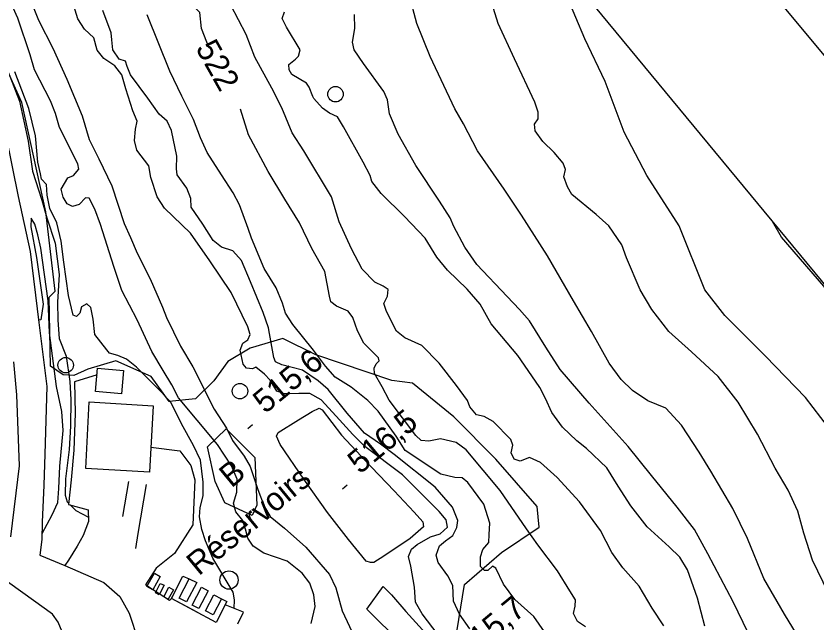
# Model space of a CAD drawing. Extents: x 347059 to 352153, y 6073752 to 6078601.
# Drawn here: x 349755.8 to 349911.2, y 6077759.6 to 6077877.3 of the extents above; entities that cross this region are included whole.
import ezdxf

# ---------------------------------------------------------------- set-up
doc = ezdxf.new("R2010")
doc.units = 0
for name, color, linetype in [('Level 1', 7, 'Continuous'), ('Level 19', 7, 'Continuous'), ('Level 2', 7, 'Continuous'), ('Level 21', 7, 'Continuous'), ('Level 3', 7, 'Continuous'), ('Level 31', 7, 'Continuous'), ('Level 33', 7, 'Continuous'), ('Level 36', 7, 'Continuous'), ('Level 37', 7, 'Continuous'), ('Level 44', 7, 'Continuous'), ('Level 60', 7, 'Continuous')]:
    doc.layers.add(name, color=color, linetype=linetype)

msp = doc.modelspace()

# ---------------------------------------------------------------- linework, layer by layer
at = {"layer": 'Level 1'}
for points in [[(349908.65, 6077755.14), (349904.89, 6077761.25), (349900.85, 6077768.19), (349897.7, 6077775.98), (349894.86, 6077781.79), (349890.56, 6077789.03), (349888.3, 6077792.7), (349884.9, 6077797.91), (349881.88, 6077801.21), (349878.39, 6077802.67), (349875.39, 6077804.67), (349873.2, 6077806.81), (349870.83, 6077809.98), (349867.44, 6077816.13), (349863.96, 6077822.07), (349858.87, 6077830.74), (349853.84, 6077838.69), (349850.49, 6077843.68), (349845.34, 6077851.13), (349842.59, 6077856.35), (349840.93, 6077859.31), (349836.12, 6077869.41), (349833.56, 6077875.84), (349831.65, 6077882.93)], [(349858.31, 6077757.85), (349856.26, 6077760.8), (349852.56, 6077764.11), (349850.36, 6077767.07), (349848.84, 6077770.19), (349848.23, 6077770.6), (349847.33, 6077769.74), (349846.67, 6077769.72), (349845.88, 6077770.52), (349845.92, 6077772.41), (349846.35, 6077773.83), (349847.51, 6077775.18), (349847.59, 6077776.7), (349847.73, 6077778.94), (349846.56, 6077782.61), (349843.46, 6077786.81), (349842.31, 6077787.72), (349840.92, 6077787.77), (349838.21, 6077788.44), (349831.28, 6077793.05), (349829.51, 6077795.83), (349826.03, 6077800.64), (349824.04, 6077802.71), (349820.79, 6077805.32), (349817.69, 6077807.27), (349815.79, 6077809.4), (349813.46, 6077812.51), (349809.49, 6077817.45), (349808.03, 6077819.68), (349807.49, 6077821.62), (349806.25, 6077824.57), (349803.92, 6077828.33), (349801.43, 6077834.22), (349800.81, 6077836.1), (349799.15, 6077840.68), (349797.91, 6077842.97), (349795.63, 6077846.51), (349792.84, 6077850.83), (349791.59, 6077853.63), (349790.19, 6077857.24), (349787.93, 6077861.72), (349785.64, 6077866.58), (349781.24, 6077877.5)], [(349798.1, 6077762.36), (349798.18, 6077764.03), (349797.89, 6077765.52), (349793.98, 6077772.17), (349792.55, 6077775.52), (349791.81, 6077777.71), (349791.39, 6077780.17), (349791.49, 6077781.99), (349792.08, 6077784.21), (349792.05, 6077786.85), (349791.59, 6077791.14), (349790.18, 6077793.98), (349787.87, 6077798.21), (349785.84, 6077802.27), (349783.99, 6077804.34), (349779.16, 6077809.16), (349777.18, 6077810.72), (349775.49, 6077811.46), (349773.91, 6077811.89), (349773.39, 6077812.52), (349771.03, 6077815.51), (349770.74, 6077818.47), (349770.3, 6077820.78), (349769.49, 6077821.44), (349768.47, 6077820.87), (349768.13, 6077819.65), (349767.48, 6077818.98), (349766.84, 6077819.25), (349765.97, 6077823.06), (349765.06, 6077829.52), (349764.51, 6077833.59), (349763.69, 6077837.18), (349762.34, 6077839.94), (349761.79, 6077842.55), (349761.7, 6077844.61), (349760.7, 6077845.65), (349760.51, 6077846.69), (349759.99, 6077848.93), (349759.54, 6077854.02), (349758.23, 6077859.34), (349755.55, 6077866.46)]]:
    msp.add_lwpolyline(points, dxfattribs=at)
at = {"layer": 'Level 19'}
for points in [[(349771.49, 6077807.7), (349767.11, 6077806.35), (349767.26, 6077800.2), (349767, 6077793.1), (349766.48, 6077787.3), (349765.98, 6077782.56), (349769.79, 6077781.53), (349769.83, 6077779.22), (349768.81, 6077776.55), (349767.6, 6077774.47), (349765.96, 6077771.73), (349765.22, 6077770.75)], [(349781.94, 6077793.68), (349787.58, 6077792.98), (349789.66, 6077790.13), (349790.44, 6077787.3), (349790.08, 6077778.61), (349786.51, 6077773.04), (349782.98, 6077770.22), (349780.89, 6077766.97)], [(349785.96, 6077764.32), (349785.56, 6077763.9), (349782.22, 6077766.08), (349780.89, 6077766.97)], [(349839.8, 6077720.48), (349843.02, 6077722.81), (349844.25, 6077724.74), (349845.07, 6077727.52), (349844.33, 6077733.95), (349842.65, 6077740.78), (349839.99, 6077746.27), (349834.89, 6077751.73), (349827.89, 6077758.22), (349826.5, 6077759.6), (349823.84, 6077762.24), (349826.99, 6077766.62), (349828.64, 6077765), (349831.38, 6077761.83), (349837.88, 6077754.69), (349841.92, 6077749.61), (349845.38, 6077744.5), (349847.54, 6077739.87), (349849.18, 6077733.08), (349850.79, 6077727.76), (349853.29, 6077724.24), (349853.4, 6077722.83), (349851.52, 6077718.63), (349848.41, 6077714.48)], [(349798.79, 6077759.43), (349799.89, 6077761.64), (349796.32, 6077763.08)]]:
    msp.add_lwpolyline(points, dxfattribs=at)
at = {"layer": 'Level 2'}
for points in [[(349793.23, 6077871.05), (349791.73, 6077874.87), (349791.45, 6077877.94), (349789.07, 6077880.47), (349786.76, 6077882.12), (349786.1, 6077883.56), (349785.54, 6077886.8), (349784.04, 6077892.3), (349783.35, 6077895.56), (349782.73, 6077899.68), (349782.18, 6077903.72), (349780.37, 6077908.95), (349779.46, 6077914.55), (349778.96, 6077922.72), (349778.76, 6077928.76), (349777.82, 6077935.52), (349777.06, 6077940.3), (349777.08, 6077950.9), (349776.37, 6077961.41), (349776.28, 6077965.09)], [(349756.14, 6077876.85), (349753.13, 6077883.55), (349748.75, 6077893.51), (349744.12, 6077902.32), (349742.88, 6077906.88), (349742.88, 6077911.27), (349743, 6077920.69), (349743.07, 6077924.34), (349743.22, 6077931.78), (349743.83, 6077937.21), (349743.8, 6077938.24)], [(349952.21, 6077714.01), (349940.56, 6077731.19), (349933.43, 6077744.22), (349930.23, 6077752.86), (349926.1, 6077763.89), (349922.2, 6077771.44), (349920.24, 6077777.95), (349920.11, 6077782.58), (349917.9, 6077790.98), (349914.87, 6077795.57), (349908.97, 6077803.29), (349901.21, 6077811.32), (349893.29, 6077819.22), (349889.43, 6077824.16), (349884.43, 6077836.56), (349878.15, 6077846.32), (349873.77, 6077854.77), (349870.11, 6077864.59), (349866.15, 6077872.85), (349862.63, 6077881.22), (349860, 6077888.93)], [(349913.39, 6077765.36), (349910.32, 6077771.76), (349908.66, 6077776.96), (349907.48, 6077781.25), (349905.56, 6077785.31), (349903.08, 6077789.57), (349899.67, 6077796.22), (349895.86, 6077802.4), (349891.99, 6077807.36), (349886.81, 6077812.14), (349882.41, 6077816.13), (349879.13, 6077820.38), (349876.9, 6077824.18), (349874.25, 6077830.4), (349873.34, 6077832.93), (349870.8, 6077836.62), (349868.33, 6077838.78), (349863.64, 6077842.65), (349862.77, 6077844.17), (349862.09, 6077846.1), (349862.38, 6077847.52), (349861.92, 6077848.71), (349860.17, 6077850.81), (349857.98, 6077852.95), (349856.52, 6077855.02), (349856.36, 6077856.33), (349857.11, 6077857.35), (349857.1, 6077858.65), (349856.42, 6077860.58), (349852.47, 6077869), (349849.3, 6077875.84), (349847.44, 6077881.91)], [(349747.91, 6077880.11), (349751.44, 6077872.61), (349754.58, 6077865.59), (349756.45, 6077860.74), (349758.12, 6077853.03), (349758.94, 6077847.17), (349760.75, 6077841.58), (349761.73, 6077838.12), (349763.38, 6077833.21), (349764.11, 6077827.13), (349763.8, 6077821.8), (349763.89, 6077818.27), (349764.13, 6077814.73), (349765.49, 6077811.31), (349766.18, 6077806.41), (349766.42, 6077802.87), (349766.36, 6077797.74), (349766.06, 6077793.21), (349765.35, 6077787.55), (349765.32, 6077784.33), (349765.71, 6077783.05), (349766, 6077782.76)], [(349758.95, 6077879.35), (349760.13, 6077876.47), (349762.9, 6077871.05), (349765.6, 6077865.04), (349768.57, 6077857.92), (349769.95, 6077853.35), (349771.85, 6077849.6), (349774.34, 6077844.34), (349776.77, 6077837.05), (349777.97, 6077834.31), (349779.28, 6077831.28), (349781.8, 6077826.31), (349784.19, 6077820.84), (349784.95, 6077818.8), (349787.7, 6077813.23), (349790.09, 6077809.22), (349794.2, 6077801.04), (349796.62, 6077797.32), (349797.78, 6077794.96), (349800.05, 6077791.91), (349801.17, 6077789.91), (349802.71, 6077785.46), (349803.93, 6077782.21), (349805.06, 6077780.21), (349807.85, 6077777.99), (349812.03, 6077774.26), (349816.58, 6077768.97), (349817.79, 6077766.37), (349819.04, 6077761.95), (349822.38, 6077754.86)], [(349812.76, 6077804.08), (349810.63, 6077804.05), (349807.84, 6077804), (349806.35, 6077804.5), (349805.09, 6077806.65), (349803.96, 6077807.85), (349802.33, 6077809.16), (349801.64, 6077808.85), (349800.48, 6077808.96), (349799.83, 6077809.74), (349799.29, 6077812.49), (349799.79, 6077813.83), (349800.73, 6077814.48), (349801.21, 6077815.53), (349800.77, 6077817.03), (349797.54, 6077823.66), (349793.38, 6077829.78), (349789.59, 6077835.15), (349784.58, 6077840.04), (349783.18, 6077842.2), (349781.94, 6077845.95), (349781.51, 6077848.25), (349779.24, 6077851.29), (349778.77, 6077853.16), (349778.98, 6077855.33), (349779.28, 6077856.91), (349778.45, 6077858.87), (349777.05, 6077863.15), (349776.29, 6077865.84), (349774.93, 6077867.64), (349772.8, 6077869.07), (349771.49, 6077870.64), (349770.84, 6077873.03), (349769.03, 6077874.72), (349767.77, 6077876.72), (349766.99, 6077879.27)], [(349831.2, 6077814.89), (349829.58, 6077816.19), (349827.62, 6077819.99), (349827.12, 6077821.56), (349827.84, 6077822.94), (349827.97, 6077824.24), (349827.02, 6077824.9), (349825.42, 6077825.69), (349822.96, 6077828.16), (349820.88, 6077832.11), (349818.48, 6077837.39), (349817, 6077842.24), (349811.61, 6077851.12), (349809.33, 6077854.65), (349807.33, 6077859.47), (349805.38, 6077863.26), (349802.11, 6077869.27), (349800.44, 6077873.7), (349797.43, 6077879.39)], [(349829.13, 6077792.22), (349826.48, 6077794.27), (349823.39, 6077796.37), (349820.04, 6077800.23), (349816.32, 6077804.86), (349814.37, 6077806.56), (349811.34, 6077808.57), (349807.35, 6077809.65), (349806.09, 6077810.2), (349805.8, 6077811.03), (349805.28, 6077813.91), (349804.76, 6077816.8), (349803.74, 6077819.8), (349801.25, 6077825.7), (349799.54, 6077829.86), (349797.83, 6077831.75), (349795.63, 6077832.46), (349794, 6077833.76), (349792.04, 6077836.92), (349789.73, 6077840.18), (349789.68, 6077841.86), (349788.93, 6077843.89), (349787.06, 6077846.46), (349786.89, 6077847.64), (349786.98, 6077850.11), (349785.94, 6077855.08), (349785.09, 6077856.9), (349783.55, 6077858.27), (349781.37, 6077861.37), (349778.01, 6077865.89), (349777.36, 6077867.47), (349777.03, 6077868.52), (349775.75, 6077868.92), (349774.54, 6077870.71), (349774.37, 6077872.69), (349774.21, 6077874.01), (349772.59, 6077878.37)], [(349819.32, 6077855.78), (349818.13, 6077857.7), (349816.6, 6077858.41), (349815.24, 6077859.4), (349813.53, 6077861.28), (349813.35, 6077861.66), (349812.66, 6077863.46), (349812.15, 6077864.23), (349809.26, 6077865.92), (349808.77, 6077866.84), (349808.73, 6077867.85), (349810, 6077868.9), (349810.56, 6077869.5), (349810.9, 6077870.7), (349808.28, 6077875.13), (349807.43, 6077876.8), (349807.85, 6077878.06)], [(349897.81, 6077757.66), (349894.91, 6077763.7), (349890, 6077772.96), (349887.41, 6077777.68), (349884.06, 6077782.02), (349879.06, 6077788.18), (349874.52, 6077793.79), (349866.98, 6077802.19), (349861.38, 6077808.76), (349858.6, 6077813.05), (349855.4, 6077818.18), (349853.43, 6077820.38), (349851.07, 6077822.9), (349845.21, 6077829.12), (349842.85, 6077832.44), (349840.7, 6077836.46), (349839.99, 6077838.11), (349837.92, 6077841.4), (349833.37, 6077848.31), (349829.9, 6077854.39), (349828.25, 6077858.29), (349827.87, 6077861), (349827.16, 6077862.66), (349823.19, 6077868.06), (349821.35, 6077870.75), (349821.05, 6077872.22), (349821.53, 6077874.86), (349821.44, 6077877.54)], [(349813.03, 6077759.49), (349813.79, 6077762.79), (349813.57, 6077765.01), (349812.77, 6077767.27), (349811.27, 6077769.23), (349808.41, 6077771.54), (349803.86, 6077773.11), (349801.78, 6077774.46), (349800.76, 6077776.02), (349800.27, 6077777.74), (349799.78, 6077779.47), (349798.4, 6077781.13), (349797.97, 6077782.78), (349798.63, 6077784.91), (349798.66, 6077787.47), (349797.59, 6077790.05), (349794.84, 6077794.17), (349790.9, 6077798.91), (349787.28, 6077803.25), (349785.99, 6077805.78), (349784.35, 6077808.56), (349782.14, 6077812.19), (349779.3, 6077818.37), (349776.33, 6077824.04), (349774.74, 6077828.71), (349772.16, 6077836.84), (349771.06, 6077839.79), (349769.95, 6077841.93), (349769.22, 6077842), (349767.99, 6077840.71), (349766.7, 6077840.32), (349765.72, 6077840.84), (349764.9, 6077842.16), (349764.54, 6077843.72), (349765.85, 6077845.87), (349766.93, 6077846.37), (349767.93, 6077847.59), (349767.74, 6077848.63), (349764.18, 6077855.67), (349763.42, 6077858.37), (349762.48, 6077860.8), (349759.33, 6077866.85), (349758.52, 6077869.77), (349756.14, 6077876.85)], [(349823.27, 6077813.81), (349822.05, 6077816.24), (349821.13, 6077818.79), (349820.23, 6077820.03), (349817.92, 6077821.03), (349816.84, 6077821.85), (349816.58, 6077822.96), (349815.67, 6077827.76), (349813.19, 6077832.19), (349810.76, 6077837.2), (349807.93, 6077841.73), (349804.67, 6077847.1), (349800.85, 6077854.25), (349799.33, 6077859.22)], [(349889.43, 6077758.94), (349888, 6077764.36), (349886.07, 6077769.89), (349884.56, 6077772.34), (349882.5, 6077774.34), (349878.21, 6077778.19), (349875.05, 6077782.31), (349872.58, 6077786.08), (349870.38, 6077789.68), (349866.46, 6077793.43), (349864.56, 6077794.9), (349861.83, 6077797.53), (349859.71, 6077800.39), (349858.52, 6077803.11), (349857.42, 6077805.23), (349855.82, 6077807.47), (349853.16, 6077811.47), (349847.94, 6077817.58), (349845.84, 6077821.39), (349843.29, 6077824.29), (349839.5, 6077828.02), (349837.42, 6077830.52), (349835.16, 6077834.2), (349831.14, 6077838.39), (349826.63, 6077842.84), (349824.82, 6077845.17), (349824.5, 6077846.35), (349823.15, 6077848.93), (349819.32, 6077855.78)], [(349760.82, 6077776.92), (349762.78, 6077780.57), (349763.88, 6077782.94), (349764.07, 6077785.64), (349764.28, 6077789.96), (349764.89, 6077796.88), (349764.67, 6077800.57), (349763.6, 6077805.44), (349762.27, 6077815.85), (349761.99, 6077822.04), (349760.57, 6077832.23), (349760.02, 6077834.85), (349759.41, 6077836.89), (349758.71, 6077838.05), (349758.62, 6077836.37), (349759.73, 6077830.47), (349761.04, 6077821.39), (349760.61, 6077818.35), (349760.15, 6077818.31)], [(349961.51, 6077714.06), (349959.39, 6077720.44), (349954.09, 6077728.4), (349948.46, 6077737.39), (349945.19, 6077743.87), (349941.09, 6077752.29), (349939.04, 6077760.82), (349936.09, 6077774.89), (349933.35, 6077782.33), (349928.41, 6077792.4), (349925.21, 6077801.03), (349918.12, 6077817.19), (349912.51, 6077824.87), (349904.32, 6077834.36), (349902.57, 6077837.42)], [(349881.49, 6077759.02), (349879.2, 6077762.42), (349876.7, 6077766.7), (349873.48, 6077770.25), (349871.37, 6077773.27), (349869.16, 6077777.53), (349865.11, 6077783.04), (349860.76, 6077787.77), (349857.54, 6077790.67), (349855.38, 6077791.66), (349853.56, 6077790.95), (349852.43, 6077791.34), (349851.82, 6077792.55), (349852.19, 6077794.04), (349851.79, 6077795.16), (349848.34, 6077798.66), (349846.61, 6077799.61), (349845.11, 6077799.96), (349843.81, 6077801.52), (349843.34, 6077802.73), (349841.22, 6077805.6), (349837.86, 6077809.95), (349834.48, 6077813.37), (349831.2, 6077814.89)], [(349866.26, 6077758.8), (349864.69, 6077759.88), (349863.96, 6077761.4), (349864.25, 6077762.83), (349864.3, 6077764.06), (349863.23, 6077765.83), (349860.83, 6077769.67), (349857.02, 6077774.73), (349854.84, 6077777.83), (349849.73, 6077785.25), (349843.14, 6077793.17), (349841.16, 6077794.58), (349838.16, 6077795.28), (349835.85, 6077794.83), (349834.4, 6077794.96), (349833.33, 6077795.93), (349828.16, 6077802.77), (349826.81, 6077805.36), (349825.32, 6077807.96), (349825.27, 6077808.98), (349825.65, 6077809.82), (349826.22, 6077810.42), (349826.13, 6077811.01), (349823.27, 6077813.81)], [(349837.69, 6077757.3), (349834.57, 6077761.37), (349833.25, 6077763.6), (349833.1, 6077766.53), (349832.4, 6077770.61), (349831.93, 6077772.48), (349832.51, 6077773.88), (349833.63, 6077774.81), (349836.19, 6077776.26), (349838.09, 6077776.89), (349839.46, 6077778.16), (349839.23, 6077779.57), (349837.86, 6077781.22), (349830.78, 6077788.27), (349823.47, 6077793.8), (349821.14, 6077796.12), (349817.9, 6077799.69), (349814.98, 6077802.87), (349812.76, 6077804.08)], [(349810.56, 6077798.95), (349813.22, 6077800.61), (349814.6, 6077801.22), (349815.15, 6077800.88), (349818.93, 6077796.02), (349821.77, 6077792.93), (349824.77, 6077789.82), (349829.15, 6077785.2), (349833, 6077781.07), (349834.72, 6077779.16), (349834.84, 6077778.2), (349832.27, 6077775.95), (349827.16, 6077772.53), (349825.21, 6077771.32), (349824.55, 6077771.3), (349823.69, 6077771.53), (349820.29, 6077775.77), (349816.19, 6077781.02), (349811.63, 6077787.48), (349807.01, 6077794.16), (349806.29, 6077795.82), (349806.66, 6077796.52), (349810.56, 6077798.95)], [(349843.81, 6077758.42), (349841.82, 6077761.29), (349840.68, 6077763.8), (349840.54, 6077766.87), (349839.55, 6077768.71), (349837.68, 6077771.28), (349837.31, 6077772.7), (349837.93, 6077774.54), (349839.13, 6077775.52), (349840.55, 6077776.56), (349841.29, 6077778.1), (349841.5, 6077779.47), (349840.43, 6077782.04), (349837.08, 6077785.91), (349829.13, 6077792.22)], [(349766.27, 6077782.48), (349767.39, 6077781.36), (349769.81, 6077780.08)]]:
    msp.add_lwpolyline(points, dxfattribs=at)
at = {"layer": 'Level 21'}
for points in [[(349753.81, 6077854.11), (349756.19, 6077842.27), (349758.54, 6077831.62), (349760.21, 6077817.83), (349761.76, 6077805.44), (349761.35, 6077792.33), (349761.19, 6077786.28), (349760.85, 6077779.11), (349760.8, 6077775.75), (349760.38, 6077772.74), (349765.22, 6077770.75), (349772.8, 6077767.45), (349775.93, 6077764.72), (349777.69, 6077761.45), (349779.48, 6077756.16)], [(349755.28, 6077810.24), (349755.83, 6077803.84), (349756.36, 6077790.06), (349754.7, 6077776.27)], [(349755.05, 6077661.53), (349755.8, 6077668.21), (349757.51, 6077679.77), (349759.69, 6077691.58), (349759.98, 6077693.54), (349761.34, 6077702.85), (349762.4, 6077714.09), (349762.74, 6077729.18), (349763.93, 6077738.11), (349765.13, 6077749.54), (349765.05, 6077757.1), (349763.93, 6077759.71), (349762.83, 6077761.28), (349759.17, 6077763.94), (349751.97, 6077769.01), (349744.46, 6077774.28), (349741.35, 6077775.37), (349730.35, 6077777.49), (349725.37, 6077777.26), (349724.23, 6077777.2), (349722.43, 6077775.55), (349721.54, 6077771.91)]]:
    msp.add_lwpolyline(points, dxfattribs=at)
at = {"layer": 'Level 3'}
for p, q in [((349800.75, 6077797.3), (349801.67, 6077798.07)), ((349819.11, 6077785.58), (349820.03, 6077786.35))]:
    msp.add_line(p, q, dxfattribs=at)
at = {"layer": 'Level 31'}
for points in [[(349771.6, 6077808.96), (349776.64, 6077808.52), (349776.24, 6077804), (349771.21, 6077804.45), (349771.6, 6077808.96)], [(349782.36, 6077801.67), (349781.69, 6077788.85), (349769.3, 6077789.5), (349769.97, 6077802.44), (349782.36, 6077801.67)]]:
    msp.add_lwpolyline(points, dxfattribs=at)
at = {"layer": 'Level 33'}
for points in [[(349781.16, 6077766.67), (349782.62, 6077769.25), (349783.76, 6077768.6), (349782.31, 6077766.03), (349781.16, 6077766.67)], [(349782.81, 6077765.42), (349783.75, 6077767.26), (349784.49, 6077766.89), (349783.55, 6077765.05), (349782.81, 6077765.42)], [(349787.42, 6077764.41), (349789.39, 6077768.16), (349790.83, 6077767.41), (349788.87, 6077763.65), (349787.42, 6077764.41)], [(349784.42, 6077764.67), (349785.44, 6077766.5), (349786.31, 6077766.02), (349785.29, 6077764.19), (349784.42, 6077764.67)], [(349789.92, 6077763.04), (349791.74, 6077766.52), (349793.06, 6077765.83), (349791.25, 6077762.35), (349789.92, 6077763.04)], [(349792.52, 6077761.91), (349794.18, 6077765.04), (349795.66, 6077764.25), (349794, 6077761.13), (349792.52, 6077761.91)]]:
    msp.add_lwpolyline(points, dxfattribs=at)
msp.add_circle((349797.09, 6077767.9), 1.78, dxfattribs=at)
at = {"layer": 'Level 36'}
for centre in [(349817.76, 6077862.11), (349765.4, 6077809.57), (349799.22, 6077804.53)]:
    msp.add_circle(centre, 1.5, dxfattribs=at)
at = {"layer": 'Level 37'}
for points in [[(349776.47, 6077780.23), (349777.63, 6077787.01)], [(349776.47, 6077780.23), (349777.63, 6077787.01)], [(349779.04, 6077774.02), (349779.45, 6077776.93), (349781.06, 6077786.42)], [(349779.04, 6077774.02), (349779.45, 6077776.93), (349781.06, 6077786.42)], [(349795.66, 6077764.25), (349796.64, 6077763.71), (349794.6, 6077759.66), (349785.96, 6077764.32), (349788.15, 6077768.65), (349789.39, 6077768.16)], [(349786.12, 6077764.64), (349788.15, 6077768.65), (349789.39, 6077768.16)], [(349790.93, 6077761.64), (349785.96, 6077764.32), (349786.12, 6077764.64)], [(349795.66, 6077764.25), (349796.64, 6077763.71), (349794.6, 6077759.66), (349794.45, 6077759.74)]]:
    msp.add_lwpolyline(points, dxfattribs=at)
at = {"layer": 'Level 44'}
for points in [[(349840.96, 6077755.82), (349842.76, 6077767.03), (349849.95, 6077773.21), (349857.26, 6077778.15), (349856.88, 6077782.15), (349848.88, 6077791.36), (349840.7, 6077799.52), (349832.7, 6077806.06), (349828.7, 6077806.57), (349813.91, 6077811.6), (349807.54, 6077814.76), (349801.21, 6077812.88), (349796.87, 6077810.31), (349794.15, 6077806.54), (349790.62, 6077803.01), (349785.48, 6077802.53), (349781.96, 6077807.36), (349775.15, 6077810.38), (349769.69, 6077808.81), (349766.96, 6077807.57), (349764.93, 6077807.67), (349762.45, 6077809.36), (349762.23, 6077822.75), (349763.35, 6077823.92), (349761.56, 6077839.33), (349756.88, 6077860.53), (349750.22, 6077875.1)], [(349802.1, 6077791.65), (349802.52, 6077782.39), (349801.61, 6077780.43), (349796.27, 6077782.86), (349794.43, 6077787.03), (349792.89, 6077793.71), (349796.54, 6077797.23), (349802.1, 6077791.65)]]:
    msp.add_lwpolyline(points, dxfattribs=at)
at = {"layer": 'Level 60'}
for points in [[(349811.7, 6077991.51), (350486.88, 6078550.39), (352105.73, 6076594.68), (351430.55, 6076035.79)], [(347109.95, 6075761.81), (348728.53, 6073803.05), (351407.22, 6076016.53), (349788.63, 6077975.29)]]:
    msp.add_lwpolyline(points, close=True, dxfattribs=at)

# ---------------------------------------------------------------- texts
at = {"layer": 'Level 2'}
msp.add_text('522', height=4.5, rotation=299.4123, dxfattribs=at).set_placement((349790.51, 6077871.06))
at = {"layer": 'Level 3'}
for s, p in [('515,6', (349804.11, 6077800.02)), ('516,5', (349822.47, 6077788.3)), ('515,7', (349843.43, 6077752.1))]:
    msp.add_text(s, height=4.5, rotation=39.62, dxfattribs=at).set_placement(p)
at = {"layer": 'Level 33'}
msp.add_text('Réservoirs', height=4.5, rotation=39.568, dxfattribs=at).set_placement((349791.22, 6077768.59))
at = {"layer": 'Level 44'}
msp.add_text('B', height=4.5, rotation=39.568, dxfattribs=at).set_placement((349797.56, 6077785.63))

doc.saveas('drawing.dxf')
